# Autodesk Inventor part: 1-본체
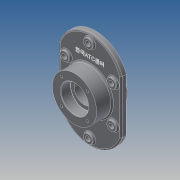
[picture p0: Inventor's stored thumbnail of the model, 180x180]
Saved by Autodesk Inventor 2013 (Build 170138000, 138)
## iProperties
Created: 2015-02
Part Number: 1-본체
Material: Generic
Document SubType Name: Modeling
Designer: kb543
Density: 1 g/cm^3
Author: kb543
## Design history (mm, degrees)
sketch "스케치1"
  geometry: L1 (-70, 60)-(-70, -60); L2 (70, 60)-(70, -60); L3 (-70, 60)-(70, 60); L4 (-70, -60)-(70, -60); A1 r 74 centre (0, 36) between (70, 60) and (-70, 60); A2 r 74 centre (0, -36) between (-70, -60) and (70, -60); 3 further points
  constraints: 8 end point, 5 point on circle, 3 horizontal alignment, 2 centre point, 2 perpendicular, 2 vertical, 1 midpoint, 1 vertical alignment
  dimensions: "d1" = 50 distance edge to line of A1 L3; "d3" = 120 distance between parallel lines of L4 L3; "d4" = 50 distance edge to line of A2 L4; "d5" = 140 distance between parallel lines of L2 L1
extrude "돌출1" new body sketch "스케치1" stored distance "d6" = 12; taper "d7" = 0 deg
sketch "스케치3"
  geometry: C1 r 50 at (0, 0); 1 further point
  constraints: 1 centre point, 1 coincident
  dimensions: "d10" = 100 diameter of C1
extrude "돌출2" join sketch "스케치3" distance "d12" = 23; taper "d13" = 0 deg
node "작업 평면1"
sketch "스케치4"
  geometry: C1 r 50 at (0, 0); 1 further point
  constraints: 1 centre point, 1 coincident
  dimensions: "d15" = 100 diameter of C1
extrude "돌출3" join sketch "스케치4" stored distance "d17" = 23; taper "d18" = 0 deg
sketch "스케치5"
  geometry: L1 (-41, -50)-(-41, 50) reference; L2 (-41, 31)-(-19, 31); L3 (-19, 31)-(-19, 22.5); L4 (-19, 22.5)-(7, 22.5); L5 (7, 22.5)-(7, 31); L6 (7, 31)-(29, 31); L7 (-41, 0)-(29, 0); L8 (29, -50)-(29, 50) reference; 1 further point
  constraints: 12 end point, 2 midpoint, 2 perpendicular, 2 point on line
  dimensions: "d19" = 62 diameter of L2 L7; "d21" = 45 diameter of L4 L7; "d22" = 62 diameter of L6 L7 (= d19); "d23" = 22 distance between parallel lines of L1 L3; "d24" = 22 distance between parallel lines of L8 L5
revolve "회전1" sketch "스케치5" stored, may be unused: angle "d25" = 90 deg
sketch "스케치6"
  geometry: L1 (70, -60)-(70, 60) reference; L2 (-70, 60)-(-70, -60) reference; L3 (-70, 0)-(70, 0); L4 (53, 56.976)-(53, -56.976); L5 (-53, -56.976)-(-53, 56.976); C1 r 50 at (0, 0) reference; C2 r 10 at (0, 93); C3 r 10 at (53, 41.677); C4 r 10 at (53, -41.677); C5 r 10 at (0, -93); C6 r 10 at (-53, 41.677); C7 r 10 at (-53, -41.677); A1 r 74 centre (0, 36) between (70, 60) and (-70, 60) reference; A2 r 74 centre (0, -36) between (-70, -60) and (70, -60) reference; A3 r 57 centre (0, 36) between (53, 56.976) and (-53, 56.976); A4 r 57 centre (0, -36) between (-53, -56.976) and (53, -56.976); 2 further points
  constraints: 8 centre point, 6 end point, 6 point on circle, 5 equal radius, 3 midpoint, 3 point on line, 2 coincident, 2 symmetric about line, 3 other
  dimensions: "d34" = 83.354 distance of C4.centre C3.centre; "d35" = 17 radial gap between concentric circles of A1 A3; "d36" = 20 diameter of C2; "d37" = 83.354 distance of C7.centre C6.centre (= d34)
extrude "돌출4" join sketch "스케치6" distance "d38" = 5; taper "d39" = 0 deg
sketch "스케치7"
  geometry: C1 r 10 at (0, 0) reference; C2 r 10 at (-53, -51.323) reference; C3 r 10 at (-53, -134.677) reference; C4 r 10 at (53, -51.323) reference; C5 r 10 at (53, -134.677) reference; C6 r 10 at (0, -186) reference; 7 further points
  constraints: 6 coincident
hole "구멍1" sketch "스케치7" at (-53, -51.323), (-53, -134.677), (53, -51.323), (53, -134.677), (0, -186), (0, 0) diameter "d40" = 11; stored, may be unused: countersink angle "d44" = 90 deg, drill point angle "d46" = 118 deg; dims "d41" = 6, "d42" = 4, "d43" = 2, "d45" = 8
sketch "스케치8"
  geometry: L1 (0, 0)-(0, 41); L2 (0, 0)-(-28.991, 28.991); C1 r 50 at (0, 0) reference; A1 r 41 centre (0, 0) between (-28.991, 28.991) and (0, 41); 1 further point
  constraints: 4 end point, 2 coincident, 2 point on circle, 1 centre point, 1 vertical
  dimensions: "d47" = 82 diameter of A1; "d49" = 45 deg angle of L1 L2
hole "구멍2" sketch "스케치8" at (-28.991, 28.991) diameter "d51" = 5.459; stored, may be unused: countersink angle "d55" = 90 deg, drill point angle "d57" = 118 deg; dims "d52" = 10, "d53" = 4, "d54" = 2, "d56" = 13
node "작업 평면2"
sketch "스케치9"
  geometry: C1 r 50 at (0, 0) reference; 1 further point
  constraints: 1 vertical alignment, 1 other
  dimensions: "d61" = 65 distance of point (0, 65) C1.centre
feature "엠보싱1" sketch "스케치9" dims "d1" = 50, "d3" = 120, "d4" = 50, "d5" = 140, "d62" = 1, "d63" = 0
fillet "모깎기1" dims "d64" = 3, "d65" = 0.3
chamfer "모따기1" distance "d67" = 1; stored, may be unused: second distance "d68" = 2, angle "d69" = 45 deg
chamfer "모따기2" distance "d70" = 1; stored, may be unused: second distance "d71" = 2, angle "d72" = 45 deg
node "솔리드1"
pattern_circular "원형 패턴1" dims angle "d59" = 360 deg
mirror "대칭1"
other parameters: "d33" = 83.35367
